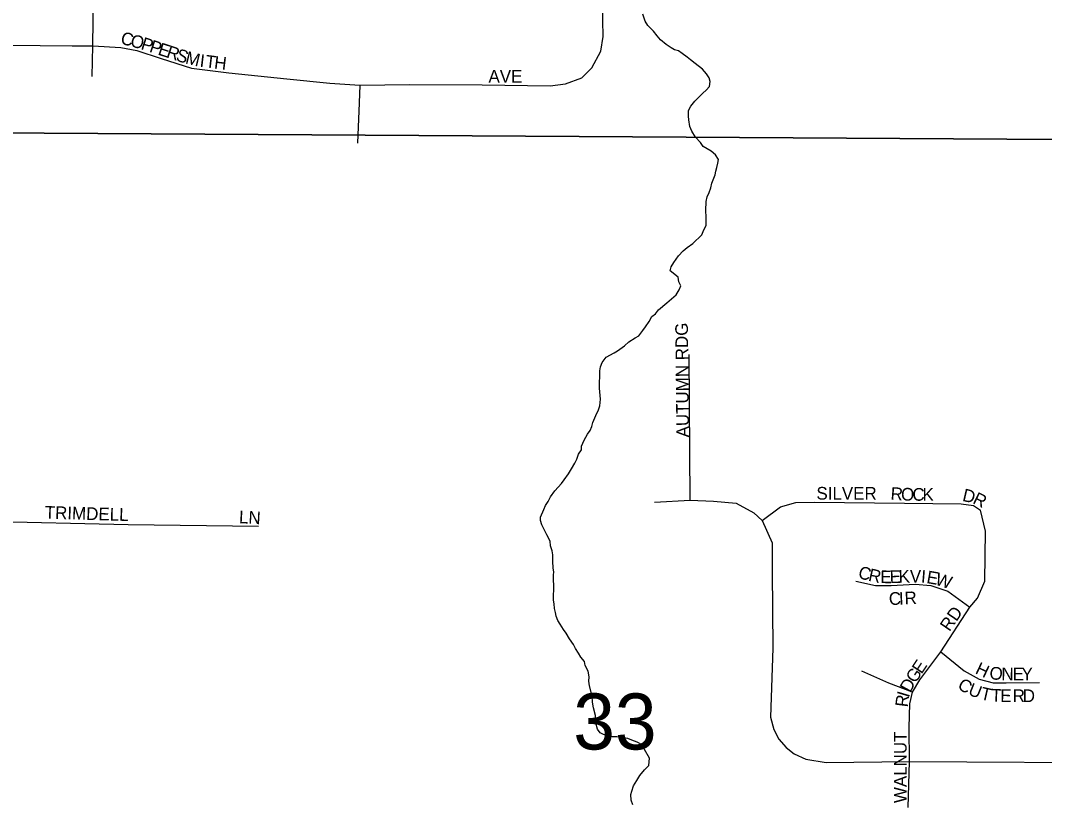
# Model space of a CAD drawing. Extents: x 8.5 to 81.5, y -1.2 to 22.4.
# Drawn here: x 51.227 to 51.992, y 16.265 to 16.85 of the extents above; entities that cross this region are included whole.
import ezdxf

# ---------------------------------------------------------------- set-up
doc = ezdxf.new("R2010")
doc.units = 0
for name, color, linetype in [('GM_X_Minor_River', 7, 'Continuous'), ('GM_X_Section', 7, 'Continuous'), ('GM_X_Section_Text', 7, 'Continuous'), ('GM_X_Township_Road', 7, 'Continuous'), ('GM_X_Township_Subdivision', 7, 'Continuous'), ('GM_X_Township_Subdivision_Text', 7, 'Continuous')]:
    doc.layers.add(name, color=color, linetype=linetype)

msp = doc.modelspace()

# ---------------------------------------------------------------- linework, layer by layer
at = {"layer": 'GM_X_Minor_River'}
for points in [[(51.72685, 16.77123), (51.72619, 16.77618), (51.72587, 16.77885), (51.72595, 16.78303), (51.72754, 16.78642), (51.73065, 16.79015), (51.73647, 16.79612), (51.73917, 16.79835), (51.7415, 16.80096), (51.74195, 16.80475), (51.74125, 16.80742), (51.73942, 16.8105), (51.73645, 16.81399), (51.73085, 16.81828), (51.72749, 16.82101), (51.72488, 16.82296), (51.72114, 16.8257), (51.71852, 16.82765), (51.7155, 16.82847), (51.71288, 16.83004), (51.70913, 16.8324), (51.70503, 16.8359), (51.70244, 16.83899), (51.69985, 16.84247), (51.69538, 16.84674), (51.69355, 16.84981), (51.69177, 16.85517)], [(51.63702, 16.38835), (51.63445, 16.39259), (51.63261, 16.39528), (51.63003, 16.39914), (51.62819, 16.40184), (51.62712, 16.40528), (51.62642, 16.40795), (51.62572, 16.41101), (51.62542, 16.41444), (51.62509, 16.4171), (51.62532, 16.4285), (51.62502, 16.43193), (51.62509, 16.43573), (51.62515, 16.43839), (51.62482, 16.44106), (51.62455, 16.44638), (51.62465, 16.45095), (51.62395, 16.454), (51.62289, 16.45782), (51.62258, 16.46125), (51.62002, 16.46586), (51.61747, 16.47085), (51.61638, 16.47354), (51.61531, 16.4766), (51.61536, 16.47926), (51.61776, 16.48491), (51.61896, 16.48793), (51.62092, 16.49093), (51.62288, 16.49431), (51.62601, 16.49881), (51.63106, 16.50441), (51.63301, 16.50703), (51.63614, 16.51153), (51.63849, 16.51529), (51.64085, 16.51942), (51.64243, 16.52243), (51.64365, 16.52621), (51.64599, 16.52958), (51.64605, 16.53224), (51.64804, 16.53676), (51.65041, 16.54128), (51.65236, 16.5439), (51.65356, 16.54692), (51.65438, 16.54994), (51.65676, 16.55521), (51.65875, 16.55935), (51.65957, 16.56238), (51.66005, 16.56731), (51.65946, 16.57568), (51.65973, 16.5886), (51.66017, 16.59163), (51.66137, 16.59465), (51.66449, 16.59877), (51.67025, 16.60208), (51.67294, 16.60354), (51.67795, 16.60724), (51.68142, 16.61021), (51.68604, 16.61316), (51.68872, 16.61463), (51.69184, 16.61875), (51.69379, 16.62137), (51.69653, 16.62549), (51.69851, 16.62925), (51.7012, 16.6311), (51.70354, 16.6341), (51.70972, 16.63929), (51.71667, 16.64523), (51.71902, 16.64899), (51.72022, 16.652), (51.71877, 16.65507), (51.71808, 16.65851), (51.71211, 16.66319), (51.71293, 16.66622), (51.71489, 16.6696), (51.71841, 16.67447), (51.7219, 16.6782), (51.72499, 16.6808), (51.72922, 16.68375), (51.7358, 16.69008), (51.7374, 16.69385), (51.73899, 16.69724), (51.73911, 16.70332), (51.73884, 16.70827), (51.73897, 16.71511), (51.7398, 16.71851), (51.74139, 16.7219), (51.7426, 16.7253), (51.74343, 16.7287), (51.74424, 16.73135), (51.74584, 16.73511), (51.74627, 16.73777), (51.74708, 16.74041), (51.74791, 16.74381), (51.74835, 16.74647), (51.74614, 16.74993), (51.74278, 16.75266), (51.73678, 16.7562), (51.73495, 16.75928), (51.73123, 16.76315), (51.72829, 16.76778), (51.72685, 16.77123)], [(51.68418, 16.26424), (51.68311, 16.26768), (51.68282, 16.27187), (51.68363, 16.27451), (51.68485, 16.27829), (51.68721, 16.28242), (51.68956, 16.28618), (51.69306, 16.29029), (51.69617, 16.29365), (51.6966, 16.2963), (51.69665, 16.29896), (51.69299, 16.3055), (51.69117, 16.30896), (51.68741, 16.31093), (51.68365, 16.31253), (51.68064, 16.31373), (51.67497, 16.3146), (51.67232, 16.31504), (51.66853, 16.31511), (51.6655, 16.31555), (51.66249, 16.31675), (51.65986, 16.31795), (51.65802, 16.32065), (51.65659, 16.32524), (51.65633, 16.33095), (51.65493, 16.33667), (51.65426, 16.34087), (51.65397, 16.34544), (51.65185, 16.35308), (51.65154, 16.35651), (51.65161, 16.35993), (51.65094, 16.36413), (51.64875, 16.36835), (51.64806, 16.37141), (51.64546, 16.3745), (51.64363, 16.37758), (51.64142, 16.38104), (51.63997, 16.38411), (51.63702, 16.38835)]]:
    msp.add_lwpolyline(points, dxfattribs=at)
at = {"layer": 'GM_X_Section'}
for points in [[(51.21175, 17.84266), (52.21491, 17.8371), (52.20343, 16.76022), (51.20445, 16.76644)], [(51.20445, 16.76644), (52.20343, 16.76022), (52.20331, 15.76418), (51.19552, 15.7645)]]:
    msp.add_lwpolyline(points, close=True, dxfattribs=at)
at = {"layer": 'GM_X_Township_Road'}
msp.add_lwpolyline([(51.70048, 16.49047), (51.72713, 16.49189), (51.74455, 16.49118), (51.76161, 16.48976), (51.77476, 16.4823), (51.78081, 16.47661), (51.78827, 16.4599), (51.78827, 16.43858), (51.78899, 16.38135), (51.78702, 16.32965), (51.78961, 16.32057), (51.79334, 16.31328), (51.79885, 16.30697), (51.80471, 16.30226), (51.81342, 16.29826), (51.8287, 16.29586), (51.89095, 16.29649), (52.06261, 16.29569), (52.08629, 16.29569), (52.09824, 16.29092), (52.10899, 16.28137), (52.11934, 16.2736), (52.12115, 16.27282)], dxfattribs=at)
at = {"layer": 'GM_X_Township_Subdivision'}
for points in [[(51.64631, 16.80755), (51.65371, 16.81506), (51.66038, 16.82744), (51.66218, 16.83833), (51.66157, 16.86231), (51.66368, 16.90249), (51.66156, 16.92574), (51.65835, 16.93858), (51.65627, 16.94689), (51.64887, 16.96698), (51.6425, 16.98134), (51.63573, 16.99509), (51.62749, 16.99953)], [(51.28033, 16.8085), (51.28096, 16.83146), (51.28128, 16.86932), (51.28149, 16.89915), (51.28081, 16.94267), (51.28291, 16.95536), (51.28822, 16.97016), (51.29989, 16.98776)], [(51.20344, 16.83199), (51.24161, 16.83167), (51.26541, 16.83146), (51.27293, 16.83146)], [(51.27293, 16.83146), (51.28096, 16.83146), (51.3017, 16.83018), (51.31364, 16.82786), (51.33184, 16.82194), (51.35447, 16.81474), (51.3825, 16.81125), (51.42588, 16.80681), (51.45803, 16.80364), (51.48046, 16.80194), (51.51758, 16.80247), (51.57163, 16.80237), (51.62251, 16.80163), (51.63404, 16.80301), (51.64631, 16.80755)], [(51.48046, 16.80194), (51.47982, 16.78883), (51.47865, 16.75858)], [(51.72713, 16.49189), (51.72643, 16.60066)], [(51.78081, 16.47661), (51.79467, 16.48691), (51.80604, 16.49011), (51.81991, 16.49047), (51.88726, 16.48958), (51.92956, 16.48923), (51.9388, 16.4878), (51.94414, 16.48443)], [(51.89007, 16.26215), (51.89095, 16.29649), (51.89073, 16.3219), (51.89118, 16.33958), (51.89313, 16.34829), (51.89882, 16.35753), (51.91429, 16.37865), (51.93596, 16.41192), (51.94189, 16.41867), (51.94717, 16.43136), (51.94787, 16.46861), (51.94414, 16.48443)], [(51.19914, 16.4762), (51.30736, 16.47359), (51.40457, 16.47252)], [(51.85084, 16.43124), (51.86565, 16.42808), (51.87728, 16.42807), (51.89527, 16.42913), (51.9069, 16.42806), (51.91959, 16.42382), (51.93596, 16.41192)], [(51.91429, 16.37865), (51.93175, 16.36428), (51.943, 16.35809), (51.95356, 16.3554), (51.96315, 16.3554), (51.98804, 16.35558)], [(51.89313, 16.34829), (51.87554, 16.35522), (51.85527, 16.36411)]]:
    msp.add_lwpolyline(points, dxfattribs=at)

# ---------------------------------------------------------------- texts
at = {"layer": 'GM_X_Section_Text'}
msp.add_text('33', height=0.041856, rotation=0.00001, dxfattribs=at).set_placement((51.63979, 16.30556))
at = {"layer": 'GM_X_Township_Subdivision_Text'}
for s, rotation, p in [('C', 345.86952, (51.30105, 16.83307)), ('O', 344.73913, (51.30827, 16.83125)), ('P', 342.37709, (51.31621, 16.82908)), ('P', 341.97115, (51.32255, 16.82707)), ('E', 341.99235, (51.3289, 16.82501)), ('R', 341.98842, (51.33523, 16.82295)), ('S', 341.99235, (51.34236, 16.82063)), ('M', 346.31458, (51.34945, 16.81836)), ('I', 353.27842, (51.3604, 16.81577)), ('T', 353.18002, (51.36454, 16.81528)), ('H', 353.16504, (51.37116, 16.81449)), ('AVE', 0.00001, (51.57645, 16.80395)), ('AUTUMN RDG', 90.60917, (51.72634, 16.53882)), ('SILVER', 0.00001, (51.82145, 16.49229)), ('R', 355.77078, (51.8766, 16.49228)), ('O', 358.37144, (51.88455, 16.4917)), ('C', 359.92285, (51.89316, 16.49146)), ('K', 359.99285, (51.90067, 16.49145)), ('D', 347.01358, (51.92999, 16.49144)), ('R', 334.14093, (51.93758, 16.48976)), ('TRIMDELL', 358.36431, (51.24484, 16.47808)), ('LN', 356.82219, (51.38988, 16.47475)), ('C', 344.69164, (51.852, 16.43387)), ('R', 347.35492, (51.8597, 16.43177)), ('E', 359.60584, (51.86921, 16.42988)), ('E', 1.92717, (51.8763, 16.42984)), ('K', 2.02124, (51.88298, 16.43006)), ('V', 359.5628, (51.8912, 16.43035)), ('I', 355.40691, (51.89935, 16.4303)), ('E', 350.14239, (51.90328, 16.42999)), ('W', 342.60185, (51.90952, 16.42893)), ('C', 1.99167, (51.87571, 16.41349)), ('I', 2.54815, (51.8833, 16.41376)), ('R', 2.58232, (51.88747, 16.41394)), ('RD', 55.48567, (51.92082, 16.39318)), ('E', 56.35539, (51.89997, 16.36147)), ('G', 56.60692, (51.89539, 16.35452)), ('H', 334.92104, (51.93944, 16.36264)), ('O', 354.60876, (51.9504, 16.35818)), ('N', 359.57615, (51.95959, 16.35735)), ('E', 359.99563, (51.968, 16.35729)), ('Y', 359.99285, (51.97466, 16.35729)), ('D', 61.09824, (51.89146, 16.3474)), ('C', 328.04095, (51.92618, 16.35158)), ('I', 73.47235, (51.89048, 16.3439)), ('U', 338.08945, (51.93416, 16.34679)), ('T', 347.22908, (51.94347, 16.34319)), ('T', 357.35266, (51.95177, 16.34148)), ('E', 358.75144, (51.95869, 16.34116)), ('R', 359.97032, (51.96807, 16.341)), ('D', 359.99285, (51.97558, 16.34099)), ('R', 82.96235, (51.88965, 16.33686)), ('WALNUT', 90, (51.88883, 16.2655))]:
    msp.add_text(s, height=0.00947, rotation=rotation, dxfattribs=at).set_placement(p)

doc.saveas('drawing.dxf')
